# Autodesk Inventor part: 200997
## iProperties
Created: 2007-12
Part Number: 200997
Document SubType Name: Modeling
Designer: MM
Density: 7.85 g/cm^3
Mass: 90.2441 g
Surface Area: 99.9897 cm^2
Volume: 11.4961 cm^3
Material: Steel
Description: CORNER BRACKET
Component Category: Lower Component
Author: MM
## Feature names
1. TaggingFeature2
